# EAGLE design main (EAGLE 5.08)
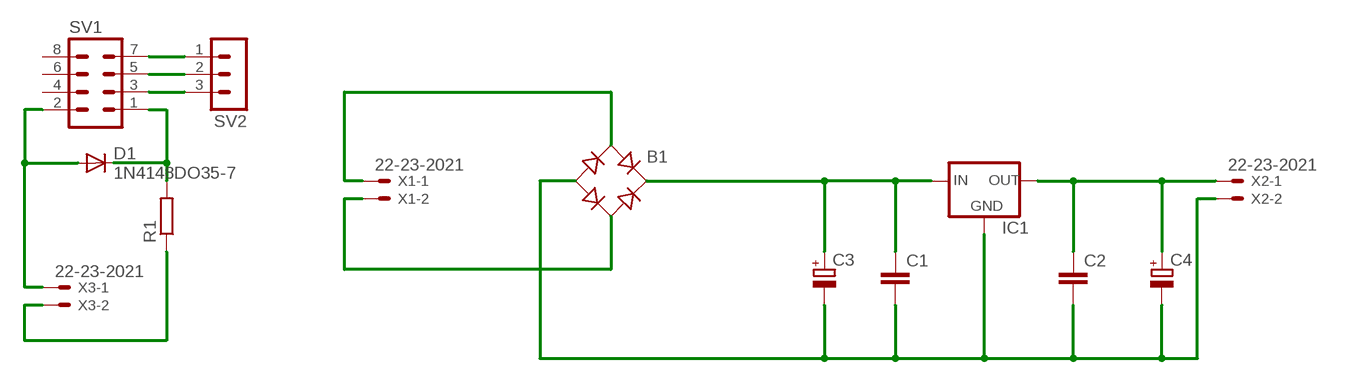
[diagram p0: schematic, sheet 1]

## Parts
B1  RB1A  [RB1A]
C1  C-EU025-025X050  [C025-025X050]
C2  C-EU025-025X050  [C025-025X050]
C3  CPOL-EUE2.5-6  [E2,5-6]
C4  CPOL-EUE2.5-6  [E2,5-6]
D1  1N4148DO35-7  [DO35-7]
IC1  78XXS  [78XXS]
R1  R-EU_0204/2V  [0204V]
SV1  MA04-2  [MA04-2]
SV2  MA03-1  [MA03-1]
X1  22-23-2021  [22-23-2021]
X2  22-23-2021  [22-23-2021]
X3  22-23-2021  [22-23-2021]

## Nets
N$1: B1.+ C1.1 C3.+ IC1.IN
N$2: B1.- C1.2 C2.2 C3.- C4.- IC1.GND X2.2
N$3: C2.1 C4.+ IC1.OUT X2.1
N$4: B1.AC1 X1.1
N$5: B1.AC2 X1.2
N$6: SV1.7 SV2.1
N$7: SV1.5 SV2.2
N$8: SV1.3 SV2.3
N$9: D1.A SV1.2 X3.1
N$10: D1.C R1.2 SV1.1
N$11: R1.1 X3.2
Unconnected: SV1.4 SV1.6 SV1.8

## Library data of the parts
B1 = rectifier:RB1A: RECTIFIER 1 A
C1 C2 = rcl:C-EU: CAPACITOR, European symbol
C3 C4 = rcl:CPOL-EU: POLARIZED CAPACITOR, European symbol
D1 = diode:1N4148: DIODE
IC1 = v-reg:78XXS: VOLTAGE REGULATOR
R1 = rcl:R-EU_: RESISTOR, European symbol
SV1 = con-lstb:MA04-2: PIN HEADER
SV2 = con-lstb:MA03-1: PIN HEADER
X1-X3 = con-molex:22-23-2021: .100" (2.54mm) Center Header - 2 Pin

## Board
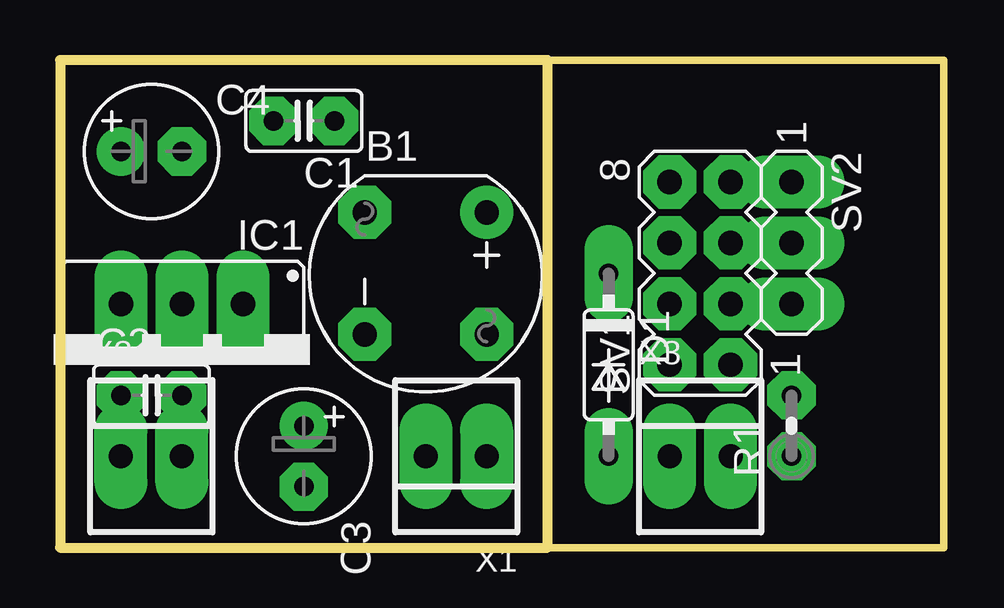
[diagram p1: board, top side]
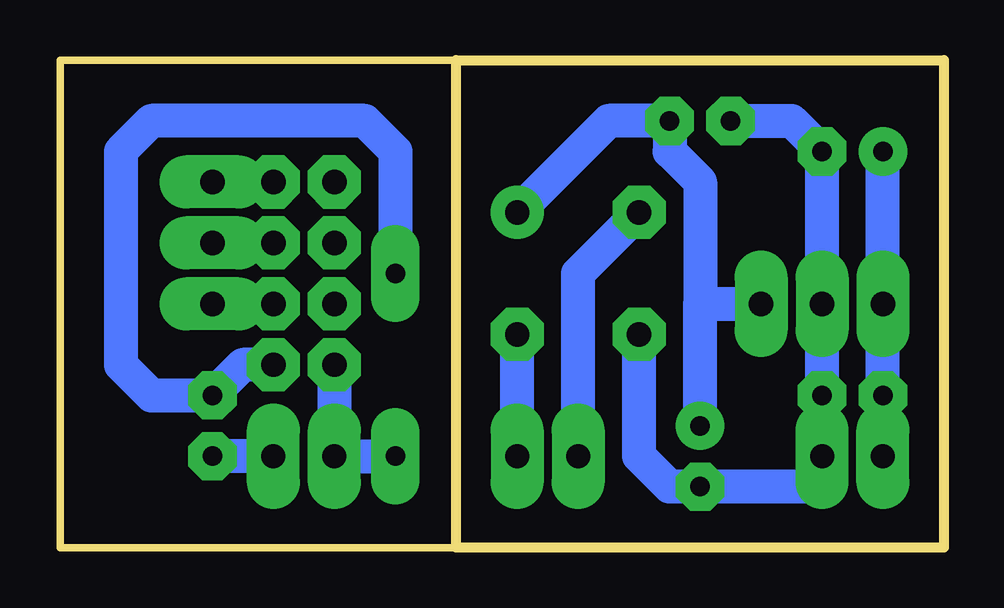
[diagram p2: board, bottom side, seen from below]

Size 36.83 x 20.32 mm. Coordinates in mm from the lower left corner, seen from the top.
Outline: 20.32,0 0,0 0,20.32 20.32,20.32
Outline: 20.32,0 20.32,20.32
Outline: 20.32,20.32 36.83,20.32 36.83,0 20.32,0
Copper layers (1*16): Top 1mm / dielectric 1.5mm / Bottom 1mm
Design rules "DRC settings middle": minimum track width 1.2mm, minimum drill 24mil, track to track 0.4mm, track to pad 0.4mm, pad to pad 0.4mm, via to via 0.4mm, smd to smd 8mil, copper to edge 0.5mm, drill to drill 0.5mm, minimum pad ring 0.6mm, minimum via ring 1mm, stop-mask expansion 4mil, vias tented up to drill 0mil, thermal gap 10mil

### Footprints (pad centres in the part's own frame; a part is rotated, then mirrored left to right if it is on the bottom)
RB1A = drill 1.016 round: + -2.54,2.54 | drill 1.016 octagon: - 2.54,-2.54; AC1 2.54,2.54; AC2 -2.54,-2.54
C025-025X050 = drill 0.813 octagon: 1 -1.27,0; 2 1.27,0
E2,5-6 = drill 0.813 pad 1.6 round: + -1.27,0 | drill 0.813 pad 1.6 octagon: - 1.27,0
DO35-7 = drill 0.813 long: A 3.81,0; C -3.81,0
78XXS = drill 1.016 long: GND 0,-2.54; IN -2.54,-2.54; OUT 2.54,-2.54
0204V = drill 0.813 octagon: 1 -1.27,0; 2 1.27,0
MA04-2 = drill 1.016 octagon: 1 -3.81,-1.27; 2 -3.81,1.27; 3 -1.27,-1.27; 4 -1.27,1.27; 5 1.27,-1.27; 6 1.27,1.27; 7 3.81,-1.27; 8 3.81,1.27
MA03-1 = drill 1.016 long: 1 -2.54,0; 2 0,0; 3 2.54,0
22-23-2021 = drill 1 long: 1 -1.27,0; 2 1.27,0

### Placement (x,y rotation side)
B1  15.24,11.43 270 top
C1  10.16,17.78 180 top
C2  3.81,6.35 0 top
C3  10.16,3.81 270 top
C4  3.81,16.51 0 top
D1  22.86,7.62 270 top
IC1  5.08,7.62 180 top
R1  30.48,5.08 90 top
SV1  26.67,11.43 90 top
SV2  30.48,12.7 270 top
X1  16.51,3.81 180 top
X2  3.81,3.81 0 top
X3  26.67,3.81 0 top

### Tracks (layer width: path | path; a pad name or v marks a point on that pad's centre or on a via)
N$1
  Bottom 1.422: 10.16,10.16 IC1.IN | C3.+ 10.16,10.16 | B1.+ 13.97,17.78 C1.1 11.43,16.51 10.16,15.24 10.16,10.16
N$2
  Bottom 1.422: B1.- 12.7,3.81 11.43,2.54 C3.- 5.08,2.54 X2.2 C2.2 IC1.GND C4.- 6.35,17.78 C1.2
N$3
  Bottom 1.422: C4.+ IC1.OUT C2.1 X2.1
N$4
  Bottom 1.422: X1.1 B1.AC1
N$5
  Bottom 1.422: B1.AC2 15.24,11.43 X1.2
N$6
  Bottom 1.422: SV1.7 SV2.1
N$7
  Bottom 1.422: SV1.5 SV2.2
N$8
  Bottom 1.422: SV1.3 SV2.3
N$9
  Bottom 1.422: SV1.2 X3.1 D1.A
N$10
  Bottom 1.422: D1.C 22.86,16.51 24.13,17.78 33.02,17.78 34.29,16.51 34.29,7.62 33.02,6.35 R1.2 29.21,7.62 SV1.1
N$11
  Bottom 1.422: X3.2 R1.1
